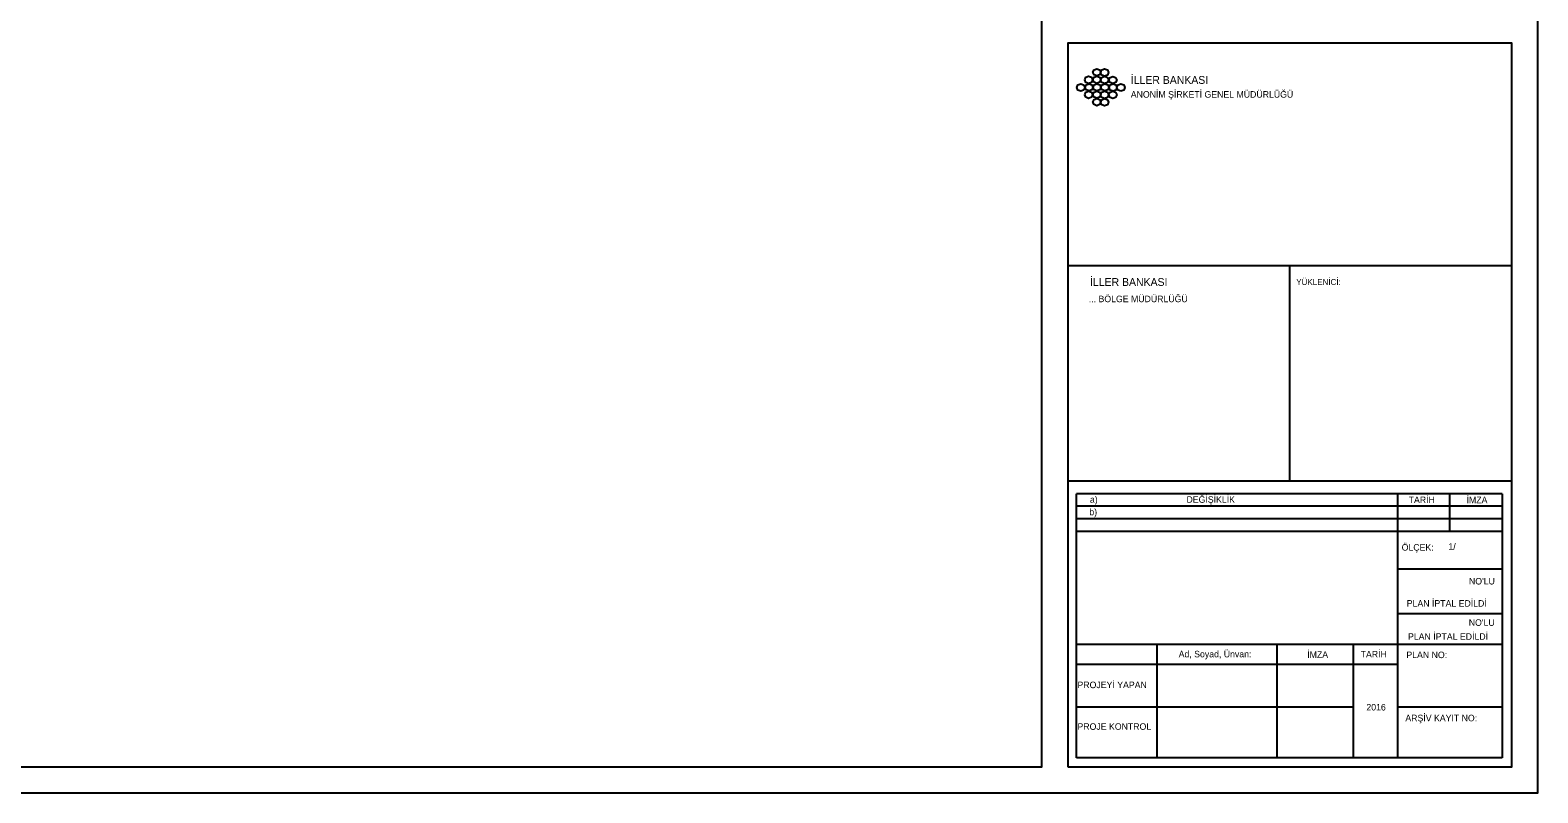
# Model space of a CAD drawing. Extents: x -10 to 1145, y -10 to 821.
# Drawn here: x 568 to 1145, y -10 to 282 of the extents above; entities that cross this region are included whole.
import ezdxf

# ---------------------------------------------------------------- set-up
doc = ezdxf.new("R2010")
doc.units = 0
for name, color, linetype in [('Baslik', 7, 'Continuous'), ('Level 50', 7, 'Continuous'), ('Level 51', 7, 'Continuous'), ('Level 53', 7, 'Continuous')]:
    doc.layers.add(name, color=color, linetype=linetype)

msp = doc.modelspace()

# ---------------------------------------------------------------- linework, layer by layer
at = {"layer": 'Baslik'}
for p, q in [((965, 191.88), (1135, 191.88)), ((1050, 109.32), (1050, 191.88)), ((1131.33, 109.32), (965, 109.32)), ((1131.33, 104.51), (968.31, 104.51)), ((968.31, 3.37), (968.31, 104.51)), ((1091.33, 3.37), (1091.33, 104.51)), ((1111.33, 90.08), (1111.33, 104.51)), ((1134.48, 109.32), (1131.33, 109.32)), ((1131.33, 104.51), (1131.33, 3.37)), ((1131.33, 99.7), (968.31, 99.7)), ((1131.33, 94.89), (968.31, 94.89)), ((1131.33, 90.08), (968.31, 90.08)), ((1131.33, 75.65), (1091.33, 75.65)), ((1131.33, 58.53), (1091.33, 58.53)), ((1131.33, 46.8), (968.31, 46.8)), ((999.2, 3.37), (999.2, 46.8)), ((1045.17, 3.37), (1045.17, 46.8)), ((1074.33, 3.37), (1074.33, 46.8)), ((1091.33, 39.11), (968.31, 39.11)), ((1074.33, 22.76), (968.31, 22.76)), ((1131.33, 22.76), (1091.33, 22.76)), ((1131.33, 3.37), (968.31, 3.37))]:
    msp.add_line(p, q, dxfattribs=at)
for points in [[(977.59, 265.86), (977.14, 264.88), (976.07, 264.47), (975, 264.88), (974.55, 265.86), (975, 266.84), (976.07, 267.25), (977.14, 266.84)], [(977.53, 265.79), (977.97, 266.77), (979.04, 267.18), (980.12, 266.77), (980.56, 265.79), (980.12, 264.8), (979.04, 264.4), (977.97, 264.8)], [(970.99, 259.06), (969.92, 258.65), (968.84, 259.06), (968.4, 260.04), (968.84, 261.02), (969.92, 261.43), (970.99, 261.02), (971.43, 260.04)], [(971.42, 262.97), (971.86, 263.95), (972.94, 264.36), (974.01, 263.95), (974.45, 262.97), (974.01, 261.99), (972.94, 261.58), (971.86, 261.99)], [(972.02, 261.1), (973.09, 261.51), (974.16, 261.1), (974.6, 260.12), (974.16, 259.13), (973.09, 258.73), (972.02, 259.13), (971.57, 260.12)], [(977.59, 263.01), (977.14, 262.03), (976.07, 261.62), (975, 262.03), (974.55, 263.01), (975, 263.99), (976.07, 264.4), (977.14, 263.99)], [(976.12, 261.51), (977.2, 261.1), (977.64, 260.12), (977.2, 259.14), (976.12, 258.73), (975.05, 259.14), (974.61, 260.12), (975.05, 261.1)], [(977.53, 262.94), (977.97, 263.92), (979.04, 264.33), (980.12, 263.92), (980.56, 262.94), (980.12, 261.95), (979.04, 261.55), (977.97, 261.95)], [(977.67, 260.11), (978.11, 261.1), (979.19, 261.5), (980.26, 261.1), (980.7, 260.11), (980.26, 259.13), (979.19, 258.72), (978.11, 259.13)], [(983.27, 263.9), (983.72, 262.92), (983.27, 261.93), (982.2, 261.53), (981.13, 261.93), (980.68, 262.92), (981.13, 263.9), (982.2, 264.31)], [(981.21, 261.03), (982.28, 261.44), (983.35, 261.03), (983.8, 260.05), (983.35, 259.07), (982.28, 258.66), (981.21, 259.07), (980.77, 260.05)], [(985.31, 258.67), (984.24, 259.08), (983.79, 260.06), (984.24, 261.05), (985.31, 261.45), (986.38, 261.05), (986.82, 260.06), (986.38, 259.08)], [(971.42, 257.27), (971.86, 258.26), (972.94, 258.66), (974.01, 258.26), (974.45, 257.27), (974.01, 256.29), (972.94, 255.88), (971.86, 256.29)], [(977.59, 257.31), (977.14, 256.33), (976.07, 255.92), (975, 256.33), (974.55, 257.31), (975, 258.3), (976.07, 258.7), (977.14, 258.3)], [(977.59, 254.47), (977.14, 253.48), (976.07, 253.08), (975, 253.48), (974.55, 254.47), (975, 255.45), (976.07, 255.86), (977.14, 255.45)], [(977.53, 257.24), (977.97, 258.22), (979.04, 258.63), (980.12, 258.22), (980.56, 257.24), (980.12, 256.26), (979.04, 255.85), (977.97, 256.26)], [(977.53, 254.39), (977.97, 255.38), (979.04, 255.78), (980.12, 255.38), (980.56, 254.39), (980.12, 253.41), (979.04, 253), (977.97, 253.41)], [(983.27, 258.2), (983.72, 257.22), (983.27, 256.24), (982.2, 255.83), (981.13, 256.24), (980.68, 257.22), (981.13, 258.2), (982.2, 258.61)]]:
    msp.add_lwpolyline(points, close=True, dxfattribs=at)
for points in [[(977.59, 265.86), (977.14, 264.88), (976.07, 264.47), (975, 264.88), (974.55, 265.86), (975, 266.84), (976.07, 267.25), (977.14, 266.84), (977.59, 265.86)], [(977.53, 265.79), (977.97, 266.77), (979.04, 267.18), (980.12, 266.77), (980.56, 265.79), (980.12, 264.8), (979.04, 264.4), (977.97, 264.8), (977.53, 265.79)], [(970.99, 259.06), (969.92, 258.65), (968.84, 259.06), (968.4, 260.04), (968.84, 261.02), (969.92, 261.43), (970.99, 261.02), (971.43, 260.04), (970.99, 259.06)], [(971.42, 262.97), (971.86, 263.95), (972.94, 264.36), (974.01, 263.95), (974.45, 262.97), (974.01, 261.99), (972.94, 261.58), (971.86, 261.99), (971.42, 262.97)], [(972.02, 261.1), (973.09, 261.51), (974.16, 261.1), (974.6, 260.12), (974.16, 259.13), (973.09, 258.73), (972.02, 259.13), (971.57, 260.12), (972.02, 261.1)], [(977.59, 263.01), (977.14, 262.03), (976.07, 261.62), (975, 262.03), (974.55, 263.01), (975, 263.99), (976.07, 264.4), (977.14, 263.99), (977.59, 263.01)], [(976.12, 261.51), (977.2, 261.1), (977.64, 260.12), (977.2, 259.14), (976.12, 258.73), (975.05, 259.14), (974.61, 260.12), (975.05, 261.1), (976.12, 261.51)], [(977.53, 262.94), (977.97, 263.92), (979.04, 264.33), (980.12, 263.92), (980.56, 262.94), (980.12, 261.95), (979.04, 261.55), (977.97, 261.95), (977.53, 262.94)], [(977.67, 260.11), (978.11, 261.1), (979.19, 261.5), (980.26, 261.1), (980.7, 260.11), (980.26, 259.13), (979.19, 258.72), (978.11, 259.13), (977.67, 260.11)], [(983.27, 263.9), (983.72, 262.92), (983.27, 261.93), (982.2, 261.53), (981.13, 261.93), (980.68, 262.92), (981.13, 263.9), (982.2, 264.31), (983.27, 263.9)], [(981.21, 261.03), (982.28, 261.44), (983.35, 261.03), (983.8, 260.05), (983.35, 259.07), (982.28, 258.66), (981.21, 259.07), (980.77, 260.05), (981.21, 261.03)], [(985.31, 258.67), (984.24, 259.08), (983.79, 260.06), (984.24, 261.05), (985.31, 261.45), (986.38, 261.05), (986.82, 260.06), (986.38, 259.08), (985.31, 258.67)], [(971.42, 257.27), (971.86, 258.26), (972.94, 258.66), (974.01, 258.26), (974.45, 257.27), (974.01, 256.29), (972.94, 255.88), (971.86, 256.29), (971.42, 257.27)], [(977.59, 257.31), (977.14, 256.33), (976.07, 255.92), (975, 256.33), (974.55, 257.31), (975, 258.3), (976.07, 258.7), (977.14, 258.3), (977.59, 257.31)], [(977.59, 254.47), (977.14, 253.48), (976.07, 253.08), (975, 253.48), (974.55, 254.47), (975, 255.45), (976.07, 255.86), (977.14, 255.45), (977.59, 254.47)], [(977.53, 257.24), (977.97, 258.22), (979.04, 258.63), (980.12, 258.22), (980.56, 257.24), (980.12, 256.26), (979.04, 255.85), (977.97, 256.26), (977.53, 257.24)], [(977.53, 254.39), (977.97, 255.38), (979.04, 255.78), (980.12, 255.38), (980.56, 254.39), (980.12, 253.41), (979.04, 253), (977.97, 253.41), (977.53, 254.39)], [(983.27, 258.2), (983.72, 257.22), (983.27, 256.24), (982.2, 255.83), (981.13, 256.24), (980.68, 257.22), (981.13, 258.2), (982.2, 258.61), (983.27, 258.2)]]:
    msp.add_lwpolyline(points, dxfattribs=at)
at = {"layer": 'Level 50'}
msp.add_lwpolyline([(0, 0), (955, 0), (955, 811), (0, 811)], close=True, dxfattribs=at)
at = {"layer": 'Level 51'}
msp.add_lwpolyline([(-10, -10), (1145, -10), (1145, 821), (-10, 821)], close=True, dxfattribs=at)
at = {"layer": 'Level 53'}
msp.add_lwpolyline([(965, 0), (1135, 0), (1135, 277), (965, 277)], close=True, dxfattribs=at)

# ---------------------------------------------------------------- texts
at = {"layer": 'Baslik'}
for s, height, p in [('İLLER BANKASI', 3, (989.08, 261.44)), ('ANONİM ŞİRKETİ GENEL MÜDÜRLÜĞÜ', 2.5, (989.08, 256.15)), ('İLLER BANKASI', 3, (973.47, 184.08)), ('YÜKLENİCİ:', 2.3, (1052.45, 184.43)), ('... BÖLGE MÜDÜRLÜĞÜ', 2.5, (973.01, 177.85)), ('DEĞİŞİKLİK', 2.5, (1010.41, 101.05)), ('TARİH', 2.5, (1095.52, 100.93)), ('İMZA', 2.5, (1117.7, 100.88)), ('b)', 2.5, (973.21, 96.28)), ('a)', 2.5, (973.43, 101.05)), ('ÖLÇEK:', 2.5, (1092.84, 82.73)), ('1/     ', 2.5, (1110.76, 83.06)), ("NO'LU", 2.5, (1118.61, 69.77)), ('PLAN İPTAL EDİLDİ', 2.5, (1094.79, 61.28)), ("NO'LU", 2.5, (1118.54, 53.94)), ('PLAN İPTAL EDİLDİ', 2.5, (1095.27, 48.58)), ('Ad, Soyad, Ünvan:', 2.5, (1007.42, 41.87)), ('İMZA', 2.5, (1056.67, 41.66)), ('TARİH', 2.5, (1077.13, 41.82)), ('PLAN NO:', 2.5, (1094.65, 41.58)), ('PROJEYİ YAPAN', 2.5, (968.66, 30.08)), ('2016', 2.5, (1079.32, 21.53)), ('ARŞİV KAYIT NO:', 2.5, (1094.26, 17.39)), ('PROJE KONTROL', 2.5, (968.66, 14.13))]:
    msp.add_text(s, height=height, dxfattribs=at).set_placement(p)

doc.saveas('drawing.dxf')
